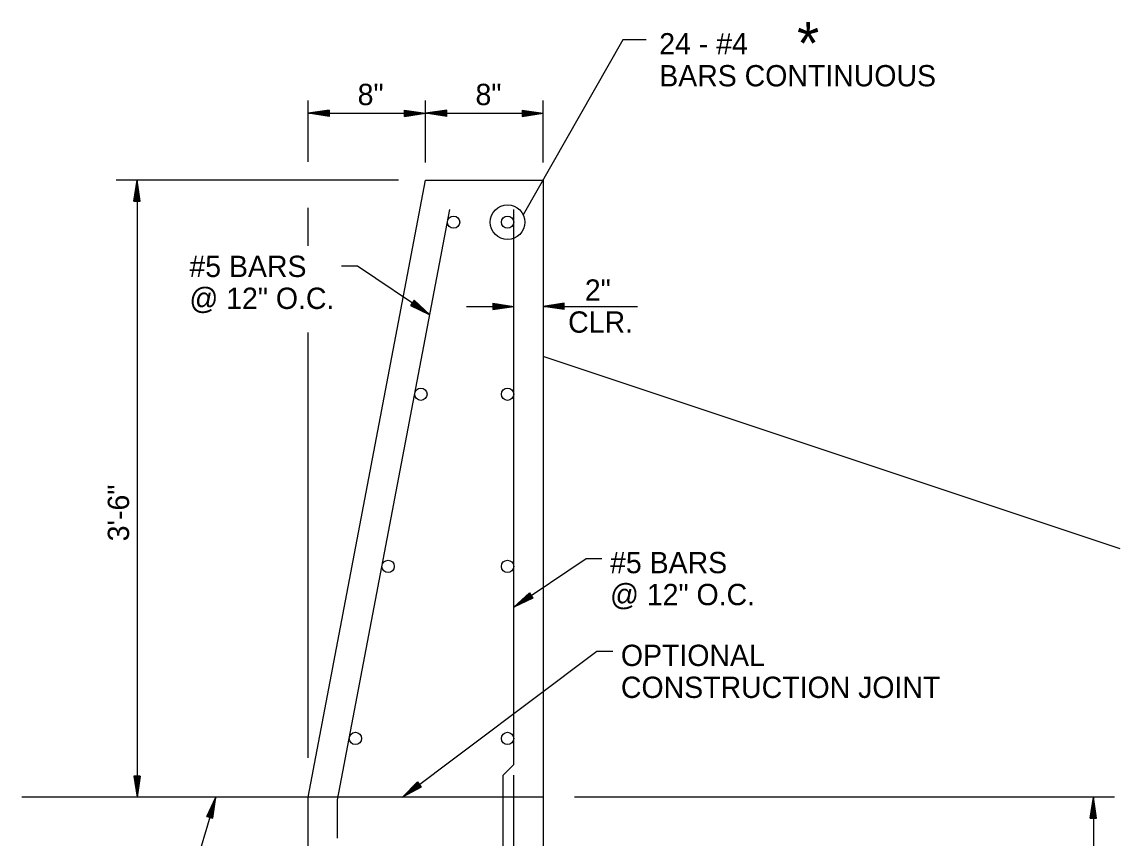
# Model space of a CAD drawing. Extents: x 757924.6 to 757955.2, y 1657125.5 to 1657146.2.
# Drawn here: x 757925.37 to 757931.6, y 1657131.81 to 1657136.44 of the extents above; entities that cross this region are included whole.
import ezdxf

# ---------------------------------------------------------------- set-up
doc = ezdxf.new("R2010")
doc.units = 0
for name, color, linetype in [('1', 7, 'Continuous'), ('2', 7, 'Continuous'), ('7', 7, 'Continuous'), ('9', 7, 'Continuous')]:
    doc.layers.add(name, color=color, linetype=linetype)

msp = doc.modelspace()

# ---------------------------------------------------------------- linework, layer by layer
at = {"layer": '1'}
for p, q in [((757926.9894, 1657132.0391), (757927.6561, 1657135.5391)), ((757927.6561, 1657135.5391), (757928.3228, 1657135.5391)), ((757927.1561, 1657132.0234), (757927.794, 1657135.3725)), ((757928.1561, 1657132.2241), (757928.1561, 1657135.3725)), ((757931.5971, 1657133.4477), (757928.3228, 1657134.5391)), ((757928.1561, 1657132.2241), (757928.0961, 1657132.1641)), ((757928.0961, 1657129.9975), (757928.0961, 1657132.1641)), ((757928.1561, 1657129.3308), (757928.1561, 1657132.1641)), ((757926.9894, 1657132.0391), (757925.3655, 1657132.0391)), ((757926.9894, 1657129.9975), (757926.9894, 1657132.0391)), ((757928.3228, 1657132.0391), (757926.9894, 1657132.0391)), ((757927.1561, 1657131.8075), (757927.1561, 1657132.0234))]:
    msp.add_line(p, q, dxfattribs=at)
msp.add_lwpolyline([(757927.6561, 1657135.5391), (757928.3228, 1657135.5391), (757928.3228, 1657129.9975)], dxfattribs=at)
for centre in [(757927.8153, 1657135.301), (757928.1212, 1657135.301), (757927.6294, 1657134.3248), (757928.1212, 1657134.3248), (757927.4434, 1657133.3486), (757928.1212, 1657133.3486), (757927.2575, 1657132.3724), (757928.1212, 1657132.3724)]:
    msp.add_circle(centre, 0.0349, dxfattribs=at)
at = {"layer": '7'}
for p, q in [((757927.1084, 1657135.9369), (757926.9894, 1657135.9185)), ((757927.1084, 1657135.9006), (757926.9894, 1657135.9185)), ((757927.1084, 1657135.9339), (757927.009, 1657135.9185)), ((757927.1084, 1657135.9042), (757927.009, 1657135.9185)), ((757927.1084, 1657135.9304), (757927.0298, 1657135.9185)), ((757927.1084, 1657135.9072), (757927.0298, 1657135.9185)), ((757927.1084, 1657135.928), (757927.0501, 1657135.9185)), ((757927.1084, 1657135.9101), (757927.0501, 1657135.9185)), ((757927.1084, 1657135.9244), (757927.0697, 1657135.9185)), ((757927.1084, 1657135.9131), (757927.0697, 1657135.9185)), ((757927.1084, 1657135.9214), (757927.0899, 1657135.9185)), ((757927.1084, 1657135.9161), (757927.0899, 1657135.9185)), ((757927.1084, 1657135.9369), (757927.1084, 1657135.9006)), ((757927.5364, 1657135.9363), (757927.6561, 1657135.9185)), ((757927.5364, 1657135.9006), (757927.5364, 1657135.9363)), ((757927.5364, 1657135.9333), (757927.6358, 1657135.9185)), ((757927.5364, 1657135.9304), (757927.6156, 1657135.9185)), ((757927.5364, 1657135.9274), (757927.5954, 1657135.9185)), ((757927.5364, 1657135.9244), (757927.5751, 1657135.9185)), ((757927.5364, 1657135.9214), (757927.5555, 1657135.9185)), ((757927.5364, 1657135.9006), (757927.6561, 1657135.9185)), ((757927.5364, 1657135.9125), (757927.5751, 1657135.9185)), ((757927.5364, 1657135.9066), (757927.6156, 1657135.9185)), ((757927.5364, 1657135.9036), (757927.6358, 1657135.9185)), ((757927.5364, 1657135.9095), (757927.5954, 1657135.9185)), ((757927.5364, 1657135.9161), (757927.5555, 1657135.9185)), ((757927.7757, 1657135.9363), (757927.6561, 1657135.9185)), ((757927.7757, 1657135.9006), (757927.6561, 1657135.9185)), ((757927.7757, 1657135.9333), (757927.6763, 1657135.9185)), ((757927.7757, 1657135.9036), (757927.6763, 1657135.9185)), ((757927.7757, 1657135.9304), (757927.6965, 1657135.9185)), ((757927.7757, 1657135.9066), (757927.6965, 1657135.9185)), ((757927.7757, 1657135.9274), (757927.7168, 1657135.9185)), ((757927.7757, 1657135.9095), (757927.7168, 1657135.9185)), ((757927.7757, 1657135.9244), (757927.737, 1657135.9185)), ((757927.7757, 1657135.9125), (757927.737, 1657135.9185)), ((757927.7757, 1657135.9214), (757927.7566, 1657135.9185)), ((757927.7757, 1657135.9161), (757927.7566, 1657135.9185)), ((757927.7757, 1657135.9006), (757927.7757, 1657135.9363)), ((757928.2037, 1657135.9369), (757928.3228, 1657135.9185)), ((757928.2037, 1657135.9369), (757928.2037, 1657135.9006)), ((757928.2037, 1657135.9339), (757928.3031, 1657135.9185)), ((757928.2037, 1657135.9304), (757928.2823, 1657135.9185)), ((757928.2037, 1657135.928), (757928.2621, 1657135.9185)), ((757928.2037, 1657135.9244), (757928.2424, 1657135.9185)), ((757928.2037, 1657135.9214), (757928.2222, 1657135.9185)), ((757928.2037, 1657135.9006), (757928.3228, 1657135.9185)), ((757928.2037, 1657135.9131), (757928.2424, 1657135.9185)), ((757928.2037, 1657135.9072), (757928.2823, 1657135.9185)), ((757928.2037, 1657135.9042), (757928.3031, 1657135.9185)), ((757928.2037, 1657135.9101), (757928.2621, 1657135.9185)), ((757928.2037, 1657135.9161), (757928.2222, 1657135.9185)), ((757926.0002, 1657135.4201), (757926.0186, 1657135.5391)), ((757926.0365, 1657135.4201), (757926.0186, 1657135.5391)), ((757926.0031, 1657135.4201), (757926.0186, 1657135.5195)), ((757926.0067, 1657135.4201), (757926.0186, 1657135.4987)), ((757926.0091, 1657135.4201), (757926.0186, 1657135.4784)), ((757926.0329, 1657135.4201), (757926.0186, 1657135.5195)), ((757926.0299, 1657135.4201), (757926.0186, 1657135.4987)), ((757926.0269, 1657135.4201), (757926.0186, 1657135.4784)), ((757926.0002, 1657135.4201), (757926.0365, 1657135.4201)), ((757926.0127, 1657135.4201), (757926.0186, 1657135.4588)), ((757926.0156, 1657135.4201), (757926.0186, 1657135.4386)), ((757926.024, 1657135.4201), (757926.0186, 1657135.4588)), ((757926.021, 1657135.4201), (757926.0186, 1657135.4386)), ((757927.5913, 1657134.8579), (757927.5712, 1657134.8277)), ((757927.5798, 1657134.8406), (757927.5969, 1657134.832)), ((757927.5827, 1657134.845), (757927.5969, 1657134.832)), ((757927.5844, 1657134.8475), (757927.6137, 1657134.8207)), ((757927.5861, 1657134.8499), (757927.63, 1657134.8098)), ((757927.5877, 1657134.8524), (757927.6468, 1657134.7986)), ((757927.5894, 1657134.8549), (757927.6636, 1657134.7874)), ((757927.5913, 1657134.8579), (757927.6804, 1657134.7761)), ((757928.037, 1657134.8419), (757928.1561, 1657134.8234)), ((757928.037, 1657134.8419), (757928.037, 1657134.8056)), ((757928.037, 1657134.8389), (757928.1364, 1657134.8234)), ((757928.4424, 1657134.8413), (757928.3228, 1657134.8234)), ((757928.4424, 1657134.8383), (757928.343, 1657134.8234)), ((757928.4424, 1657134.805), (757928.4424, 1657134.8413)), ((757927.5712, 1657134.8277), (757927.6804, 1657134.7761)), ((757927.5728, 1657134.8302), (757927.6636, 1657134.7874)), ((757927.5748, 1657134.8331), (757927.6468, 1657134.7986)), ((757927.5761, 1657134.8351), (757927.63, 1657134.8098)), ((757927.5781, 1657134.8381), (757927.6137, 1657134.8207)), ((757928.037, 1657134.8353), (757928.1156, 1657134.8234)), ((757928.037, 1657134.833), (757928.0954, 1657134.8234)), ((757928.037, 1657134.8294), (757928.0757, 1657134.8234)), ((757928.037, 1657134.8264), (757928.0555, 1657134.8234)), ((757928.037, 1657134.8056), (757928.1561, 1657134.8234)), ((757928.037, 1657134.8181), (757928.0757, 1657134.8234)), ((757928.037, 1657134.8121), (757928.1156, 1657134.8234)), ((757928.037, 1657134.8092), (757928.1364, 1657134.8234)), ((757928.037, 1657134.8151), (757928.0954, 1657134.8234)), ((757928.037, 1657134.8211), (757928.0555, 1657134.8234)), ((757928.4424, 1657134.805), (757928.3228, 1657134.8234)), ((757928.4424, 1657134.8086), (757928.343, 1657134.8234)), ((757928.4424, 1657134.8348), (757928.3638, 1657134.8234)), ((757928.4424, 1657134.8115), (757928.3638, 1657134.8234)), ((757928.4424, 1657134.8324), (757928.3835, 1657134.8234)), ((757928.4424, 1657134.8145), (757928.3835, 1657134.8234)), ((757928.4424, 1657134.8288), (757928.4031, 1657134.8234)), ((757928.4424, 1657134.8175), (757928.4031, 1657134.8234)), ((757928.4424, 1657134.8258), (757928.4233, 1657134.8234)), ((757928.4424, 1657134.8205), (757928.4233, 1657134.8234)), ((757928.2452, 1657133.1992), (757928.1561, 1657133.1175)), ((757928.2653, 1657133.169), (757928.1561, 1657133.1175)), ((757928.2471, 1657133.1962), (757928.1729, 1657133.1287)), ((757928.2637, 1657133.1715), (757928.1729, 1657133.1287)), ((757928.2488, 1657133.1937), (757928.1897, 1657133.1399)), ((757928.2617, 1657133.1744), (757928.1897, 1657133.1399)), ((757928.2505, 1657133.1913), (757928.2065, 1657133.1511)), ((757928.2604, 1657133.1764), (757928.2065, 1657133.1511)), ((757928.2521, 1657133.1888), (757928.2228, 1657133.162)), ((757928.2584, 1657133.1794), (757928.2228, 1657133.162)), ((757928.2538, 1657133.1863), (757928.2396, 1657133.1733)), ((757928.2567, 1657133.1819), (757928.2396, 1657133.1733)), ((757928.2452, 1657133.1992), (757928.2653, 1657133.169)), ((757926.0008, 1657132.1588), (757926.0186, 1657132.0391)), ((757926.0365, 1657132.1588), (757926.0008, 1657132.1588)), ((757926.0037, 1657132.1588), (757926.0186, 1657132.0594)), ((757926.0067, 1657132.1588), (757926.0186, 1657132.0796)), ((757926.0097, 1657132.1588), (757926.0186, 1657132.0999)), ((757926.0127, 1657132.1588), (757926.0186, 1657132.1201)), ((757926.0156, 1657132.1588), (757926.0186, 1657132.1397)), ((757926.0365, 1657132.1588), (757926.0186, 1657132.0391)), ((757926.0246, 1657132.1588), (757926.0186, 1657132.1201)), ((757926.0305, 1657132.1588), (757926.0186, 1657132.0796)), ((757926.0335, 1657132.1588), (757926.0186, 1657132.0594)), ((757926.0275, 1657132.1588), (757926.0186, 1657132.0999)), ((757926.021, 1657132.1588), (757926.0186, 1657132.1397)), ((757927.6096, 1657132.1254), (757927.5248, 1657132.0391)), ((757927.6312, 1657132.0963), (757927.5248, 1657132.0391)), ((757927.6117, 1657132.1225), (757927.541, 1657132.0512)), ((757927.6295, 1657132.0987), (757927.541, 1657132.0512)), ((757927.6135, 1657132.1201), (757927.5572, 1657132.0633)), ((757927.6273, 1657132.1016), (757927.5572, 1657132.0633)), ((757927.6152, 1657132.1178), (757927.5734, 1657132.0754)), ((757927.6259, 1657132.1035), (757927.5734, 1657132.0754)), ((757927.617, 1657132.1154), (757927.5891, 1657132.0872)), ((757927.6238, 1657132.1063), (757927.5891, 1657132.0872)), ((757927.6188, 1657132.113), (757927.6053, 1657132.0992)), ((757927.622, 1657132.1087), (757927.6053, 1657132.0992)), ((757927.6096, 1657132.1254), (757927.6312, 1657132.0963)), ((757926.4148, 1657131.9298), (757926.4664, 1657132.0391)), ((757926.4496, 1657131.9195), (757926.4664, 1657132.0391)), ((757931.4276, 1657131.9201), (757931.4461, 1657132.0391)), ((757931.4639, 1657131.9201), (757931.4461, 1657132.0391)), ((757926.4182, 1657131.9288), (757926.4607, 1657132.0198)), ((757926.4211, 1657131.928), (757926.4549, 1657132.0004)), ((757926.4239, 1657131.9271), (757926.4492, 1657131.981)), ((757926.441, 1657131.922), (757926.4492, 1657131.981)), ((757926.4433, 1657131.9214), (757926.4549, 1657132.0004)), ((757926.4467, 1657131.9204), (757926.4607, 1657132.0198)), ((757931.4306, 1657131.9201), (757931.4461, 1657132.0195)), ((757931.4342, 1657131.9201), (757931.4461, 1657131.9987)), ((757931.4365, 1657131.9201), (757931.4461, 1657131.9784)), ((757931.4603, 1657131.9201), (757931.4461, 1657132.0195)), ((757931.4574, 1657131.9201), (757931.4461, 1657131.9987)), ((757931.4544, 1657131.9201), (757931.4461, 1657131.9784)), ((757926.4148, 1657131.9298), (757926.4496, 1657131.9195)), ((757926.4268, 1657131.9263), (757926.4436, 1657131.9622)), ((757926.4296, 1657131.9254), (757926.4379, 1657131.9428)), ((757926.4348, 1657131.9239), (757926.4379, 1657131.9428)), ((757926.4376, 1657131.9231), (757926.4436, 1657131.9622)), ((757931.4276, 1657131.9201), (757931.4639, 1657131.9201)), ((757931.4401, 1657131.9201), (757931.4461, 1657131.9588)), ((757931.4431, 1657131.9201), (757931.4461, 1657131.9386)), ((757931.4514, 1657131.9201), (757931.4461, 1657131.9588)), ((757931.4484, 1657131.9201), (757931.4461, 1657131.9386))]:
    msp.add_line(p, q, dxfattribs=at)
at = {"layer": '9'}
for p, q in [((757928.7756, 1657136.3359), (757928.21, 1657135.3421)), ((757928.9087, 1657136.3359), (757928.7756, 1657136.3359)), ((757926.9894, 1657135.6441), (757926.9894, 1657135.9914)), ((757927.6561, 1657135.6385), (757927.6561, 1657135.9914)), ((757928.3228, 1657135.6385), (757928.3228, 1657135.9914)), ((757926.9894, 1657135.9185), (757928.3228, 1657135.9185)), ((757927.5032, 1657135.5391), (757925.8997, 1657135.5391)), ((757926.0186, 1657135.5391), (757926.0186, 1657132.0391)), ((757927.5032, 1657135.5391), (757927.0695, 1657135.5391)), ((757926.9894, 1657135.1666), (757926.9894, 1657135.3814)), ((757927.2695, 1657135.0523), (757927.1797, 1657135.0523)), ((757927.6804, 1657134.7761), (757927.2695, 1657135.0523)), ((757927.8878, 1657134.8234), (757928.1561, 1657134.8234)), ((757928.3228, 1657134.8234), (757928.8592, 1657134.8234)), ((757926.9894, 1657132.2626), (757926.9894, 1657134.6744)), ((757928.1561, 1657133.1175), (757928.567, 1657133.3936)), ((757928.567, 1657133.3936), (757928.6568, 1657133.3936)), ((757927.5248, 1657132.0391), (757928.6287, 1657132.8673)), ((757928.6287, 1657132.8673), (757928.7185, 1657132.8673)), ((757926.4664, 1657132.0391), (757926.3716, 1657131.7218)), ((757931.5661, 1657132.0391), (757928.5005, 1657132.0391)), ((757931.4461, 1657132.0391), (757931.4461, 1657129.9975))]:
    msp.add_line(p, q, dxfattribs=at)
msp.add_circle((757928.1212, 1657135.301), 0.0979, dxfattribs=at)

# ---------------------------------------------------------------- texts
at = {"layer": '2'}
for s, height, p in [('*', 0.2416, (757929.7642, 1657136.195)), ('24 - #4', 0.12081, (757928.982, 1657136.2525)), ('BARS CONTINUOUS', 0.12081, (757928.982, 1657136.0713)), ('8"', 0.12095, (757927.2705, 1657135.9649)), ('8"', 0.12095, (757927.9392, 1657135.9649)), ('#5 BARS', 0.12081, (757926.3157, 1657134.9899)), ('2"', 0.12095, (757928.5596, 1657134.8553)), ('@ 12" O.C.', 0.12081, (757926.3157, 1657134.8087)), ('CLR.', 0.12095, (757928.4649, 1657134.6739)), ('#5 BARS', 0.12081, (757928.7029, 1657133.3096)), ('@ 12" O.C.', 0.12081, (757928.7029, 1657133.1283)), ('OPTIONAL', 0.12081, (757928.7645, 1657132.7833)), ('CONSTRUCTION JOINT', 0.12081, (757928.7645, 1657132.6021))]:
    msp.add_text(s, height=height, dxfattribs=at).set_placement(p)
msp.add_text('3\'-6"', height=0.12095, rotation=90, dxfattribs=at).set_placement((757925.9733, 1657133.4904))

doc.saveas('drawing.dxf')
